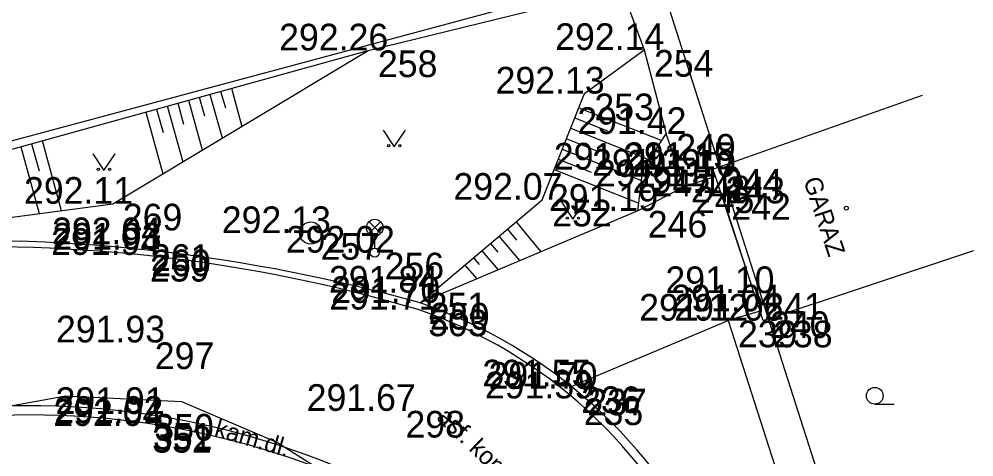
# Model space of a CAD drawing. Extents: x -599970 to -599524, y -1154772 to -1154457.
# Drawn here: x -599739.51 to -599718.03, y -1154670.86 to -1154661 of the extents above; entities that cross this region are included whole.
import ezdxf

# ---------------------------------------------------------------- set-up
doc = ezdxf.new("R2010")
doc.units = 0
for name, color, linetype in [('Z-BUDOVY', 7, 'Continuous'), ('Z-ELEKTRICKE SKRINE LAMPY', 7, 'Continuous'), ('Z-KANALIZACNI SACHTY VPUSTI', 7, 'Continuous'), ('Z-KATASTRALNI MAPA', 7, 'Continuous'), ('Z-PLOT DRATENY', 7, 'Continuous'), ('Z-PODROBNE BODY', 7, 'Continuous'), ('Z-PODROBNE BODY-CISLO', 7, 'Continuous'), ('Z-PODROBNE BODY-VYSKA', 7, 'Continuous'), ('Z-POPISY OBJEKTU A ZPEVNENYCH PLOCH', 7, 'Continuous'), ('Z-SCHODY', 7, 'Continuous'), ('Z-SRAFOVANI SVAHU', 7, 'Continuous'), ('Z-STROMY ZNACKY KULTUR', 7, 'Continuous'), ('Z-TERENNI HRANY PATY', 7, 'Continuous'), ('Z-VSTUPY VJEZDY', 7, 'Continuous'), ('Z-ZPEVNENE PLOCHY', 7, 'Continuous')]:
    doc.layers.add(name, color=color, linetype=linetype)

msp = doc.modelspace()

# ---------------------------------------------------------------- linework, layer by layer
at = {"layer": 'Z-BUDOVY'}
for p, q in [((-599723.9, -1154664.38), (-599719.19, -1154662.72)), ((-599722.77, -1154667.79), (-599718.03, -1154666.21))]:
    msp.add_line(p, q, dxfattribs=at)
msp.add_lwpolyline([(-599722.77, -1154667.79), (-599722.84, -1154667.58), (-599723.84, -1154664.55), (-599723.9, -1154664.38)], dxfattribs=at)
at = {"layer": 'Z-ELEKTRICKE SKRINE LAMPY'}
for p, q in [((-599731.642, -1154665.829), (-599731.378, -1154665.565)), ((-599731.374, -1154665.828), (-599731.638, -1154665.563)), ((-599731.51, -1154666.16), (-599731.51, -1154665.885))]:
    msp.add_line(p, q, dxfattribs=at)
for centre, radius in [((-599731.51, -1154665.698), 0.188), ((-599731.51, -1154666.26), 0.1)]:
    msp.add_circle(centre, radius, dxfattribs=at)
at = {"layer": 'Z-KANALIZACNI SACHTY VPUSTI'}
msp.add_circle((-599732.95, -1154665.82), 0.25, dxfattribs=at)
at = {"layer": 'Z-KATASTRALNI MAPA'}
for q in [(-599770.56, -1154672.04), (-599721.27, -1154672.07)]:
    msp.add_line((-599725.18, -1154659.85), q, dxfattribs=at)
msp.add_lwpolyline([(-599834.98, -1154699.48), (-599751.66, -1154673.18), (-599740.79, -1154669.9), (-599738.46, -1154669.48), (-599735.86, -1154669.61), (-599733.7, -1154670.53), (-599731.62, -1154671.85), (-599729.9, -1154673.34)], dxfattribs=at)
at = {"layer": 'Z-PLOT DRATENY'}
for points in [[(-599790.59, -1154625.68), (-599789.41, -1154629.89), (-599785.15, -1154644.86), (-599782.34, -1154653.87), (-599779.13, -1154664.86), (-599776.51, -1154673.7), (-599770.19, -1154672.08), (-599762.65, -1154670.15), (-599753.18, -1154667.49), (-599743.82, -1154665.08), (-599731.66, -1154661.71), (-599725.96, -1154660.31)], [(-599725.96, -1154660.31), (-599725.45, -1154661.7), (-599724.95, -1154663.59)], [(-599723.84, -1154664.55), (-599724.53, -1154664.77), (-599724.62, -1154664.53)], [(-599722.84, -1154667.58), (-599723.56, -1154667.79), (-599721.98, -1154672.69), (-599721.73, -1154673.41)]]:
    msp.add_lwpolyline(points, dxfattribs=at)
at = {"layer": 'Z-PODROBNE BODY'}
for p, q in [((-599731.66, -1154661.71), (-599731.66, -1154661.71)), ((-599725.45, -1154661.7), (-599725.45, -1154661.7)), ((-599726.79, -1154662.68), (-599726.79, -1154662.68)), ((-599724.95, -1154663.59), (-599724.95, -1154663.59)), ((-599725.48, -1154664.39), (-599725.48, -1154664.39)), ((-599723.9, -1154664.38), (-599723.9, -1154664.38)), ((-599724.62, -1154664.53), (-599724.62, -1154664.53)), ((-599723.84, -1154664.55), (-599723.84, -1154664.55)), ((-599724.53, -1154664.77), (-599724.53, -1154664.77)), ((-599727.74, -1154665.07), (-599727.74, -1154665.07)), ((-599723.71, -1154664.92), (-599723.71, -1154664.92)), ((-599737.4, -1154665.16), (-599737.4, -1154665.16)), ((-599725.59, -1154665.32), (-599725.59, -1154665.32)), ((-599732.95, -1154665.82), (-599732.95, -1154665.82)), ((-599736.77, -1154666.07), (-599736.77, -1154666.07)), ((-599736.76, -1154666.19), (-599736.76, -1154666.19)), ((-599736.79, -1154666.31), (-599736.79, -1154666.31)), ((-599731.51, -1154666.26), (-599731.51, -1154666.26)), ((-599730.54, -1154667.16), (-599730.54, -1154667.16)), ((-599722.97, -1154667.17), (-599722.97, -1154667.17)), ((-599730.49, -1154667.39), (-599730.49, -1154667.39)), ((-599730.53, -1154667.54), (-599730.53, -1154667.54)), ((-599722.84, -1154667.58), (-599722.84, -1154667.58)), ((-599723.56, -1154667.79), (-599723.56, -1154667.79)), ((-599722.77, -1154667.79), (-599722.77, -1154667.79)), ((-599736.68, -1154668.28), (-599736.68, -1154668.28)), ((-599727.09, -1154669.27), (-599727.09, -1154669.27)), ((-599726.95, -1154669.32), (-599726.95, -1154669.32)), ((-599727.03, -1154669.54), (-599727.03, -1154669.54)), ((-599731.04, -1154669.82), (-599731.04, -1154669.82)), ((-599736.69, -1154669.89), (-599736.69, -1154669.89)), ((-599736.74, -1154670.16), (-599736.74, -1154670.16)), ((-599736.72, -1154670.09), (-599736.72, -1154670.09))]:
    msp.add_line(p, q, dxfattribs=at)
at = {"layer": 'Z-SCHODY'}
msp.add_circle((-599720.9, -1154665.26), 0.0438, dxfattribs=at)
at = {"layer": 'Z-SRAFOVANI SVAHU'}
for points in [[(-599735.46, -1154662.76), (-599735.34, -1154663.18)], [(-599735.22, -1154662.7), (-599734.94, -1154663.68)], [(-599734.98, -1154662.63), (-599734.87, -1154663)], [(-599734.73, -1154662.56), (-599734.5, -1154663.42)], [(-599736.18, -1154662.96), (-599735.83, -1154664.22)], [(-599735.94, -1154662.9), (-599735.81, -1154663.37)], [(-599735.7, -1154662.83), (-599735.39, -1154663.95)], [(-599736.66, -1154663.1), (-599736.28, -1154664.49)], [(-599736.42, -1154663.03), (-599736.27, -1154663.56)], [(-599726.92, -1154663), (-599725.05, -1154663.74)], [(-599727.01, -1154663.23), (-599726.28, -1154663.52)], [(-599727.1, -1154663.46), (-599725.33, -1154664.17)], [(-599739.23, -1154663.81), (-599739.06, -1154664.42)], [(-599738.99, -1154663.74), (-599738.56, -1154665.31)], [(-599727.19, -1154663.7), (-599726.51, -1154663.97)], [(-599739.47, -1154663.88), (-599739.06, -1154665.38)], [(-599727.29, -1154663.93), (-599725.51, -1154664.64)], [(-599727.38, -1154664.16), (-599726.64, -1154664.45)], [(-599727.47, -1154664.39), (-599725.57, -1154665.15)], [(-599728.52, -1154665.73), (-599728.32, -1154665.98)], [(-599728.33, -1154665.57), (-599727.77, -1154666.24)], [(-599728.72, -1154665.89), (-599728.25, -1154666.44)], [(-599728.91, -1154666.05), (-599728.74, -1154666.25)], [(-599729.29, -1154666.38), (-599729.16, -1154666.53)], [(-599729.1, -1154666.22), (-599728.73, -1154666.65)], [(-599729.48, -1154666.54), (-599729.21, -1154666.85)]]:
    msp.add_lwpolyline(points, dxfattribs=at)
at = {"layer": 'Z-STROMY ZNACKY KULTUR'}
msp.add_line((-599720.26, -1154669.668), (-599719.822, -1154669.668), dxfattribs=at)
for points in [[(-599731.32, -1154663.505), (-599731.07, -1154663.88), (-599730.82, -1154663.505)], [(-599737.85, -1154664.035), (-599737.6, -1154664.41), (-599737.35, -1154664.035)], [(-599727.3, -1154665.135), (-599727.05, -1154665.51), (-599726.8, -1154665.135)]]:
    msp.add_lwpolyline(points, dxfattribs=at)
for centre, radius in [((-599731.195, -1154663.855), 0.025), ((-599730.945, -1154663.855), 0.025), ((-599737.725, -1154664.385), 0.025), ((-599737.475, -1154664.385), 0.025), ((-599727.175, -1154665.485), 0.025), ((-599726.925, -1154665.485), 0.025), ((-599720.26, -1154669.48), 0.188)]:
    msp.add_circle(centre, radius, dxfattribs=at)
at = {"layer": 'Z-TERENNI HRANY PATY'}
for points in [[(-599742.26, -1154667.02), (-599742.5, -1154665.84), (-599737.4, -1154665.16), (-599731.66, -1154661.71)], [(-599730.49, -1154667.39), (-599727.74, -1154665.07), (-599726.79, -1154662.68), (-599725.45, -1154661.7)]]:
    msp.add_lwpolyline(points, dxfattribs=at)
at = {"layer": 'Z-VSTUPY VJEZDY'}
for points in [[(-599724.62, -1154664.53), (-599724.95, -1154663.59)], [(-599722.97, -1154667.17), (-599723.71, -1154664.92)]]:
    msp.add_lwpolyline(points, dxfattribs=at)
at = {"layer": 'Z-ZPEVNENE PLOCHY'}
for points in [[(-599725.59, -1154665.32), (-599725.48, -1154664.39), (-599724.95, -1154663.59)], [(-599724.53, -1154664.77), (-599725.59, -1154665.32), (-599730.49, -1154667.39)], [(-599727.09, -1154669.27), (-599723.56, -1154667.79)]]:
    msp.add_lwpolyline(points, dxfattribs=at)
for centre, radius, start, end in [((-599740.676, -1154703.63), 37.644, 74.3013, 92.4426), ((-599740.37, -1154701.075), 34.949, 73.647, 92.8702), ((-599734.212, -1154678.135), 11.372, 25.0528, 70.8958), ((-599734.095, -1154677.842), 10.901, 24.0446, 70.9101), ((-599739.28, -1154687.811), 18.107, 64.483, 98.8632), ((-599739.271, -1154688.14), 18.229, 64.7672, 98.4821)]:
    msp.add_arc(centre, radius, start, end, dxfattribs=at)

# ---------------------------------------------------------------- texts
at = {"layer": 'Z-PODROBNE BODY-CISLO'}
for s, p in [(' 254', (-599725.45, -1154662.3)), (' 258', (-599731.66, -1154662.31)), (' 253', (-599726.79, -1154663.28)), (' 249', (-599724.95, -1154664.19)), (' 247', (-599725.48, -1154664.99)), (' 244', (-599723.9, -1154664.98)), (' 248', (-599724.62, -1154665.13)), (' 243', (-599723.84, -1154665.15)), (' 245', (-599724.53, -1154665.37)), (' 242', (-599723.71, -1154665.52)), (' 252', (-599727.74, -1154665.67)), (' 269', (-599737.4, -1154665.76)), (' 246', (-599725.59, -1154665.92)), (' 257', (-599732.95, -1154666.42)), (' 261', (-599736.77, -1154666.67)), (' 260', (-599736.76, -1154666.79)), (' 259', (-599736.79, -1154666.91)), (' 256', (-599731.51, -1154666.86)), (' 251', (-599730.54, -1154667.76)), (' 241', (-599722.97, -1154667.77)), (' 250', (-599730.49, -1154667.99)), (' 503', (-599730.53, -1154668.14)), (' 240', (-599722.84, -1154668.18)), (' 239', (-599723.56, -1154668.39)), (' 238', (-599722.77, -1154668.39)), (' 297', (-599736.68, -1154668.88)), (' 236', (-599727.09, -1154669.87)), (' 237', (-599726.95, -1154669.92)), (' 235', (-599727.03, -1154670.14)), (' 298', (-599731.04, -1154670.42)), (' 350', (-599736.69, -1154670.49)), (' 352', (-599736.74, -1154670.76)), (' 351', (-599736.72, -1154670.69))]:
    msp.add_text(s, height=0.6, dxfattribs=at).set_placement(p)
at = {"layer": 'Z-PODROBNE BODY-VYSKA'}
for s, p in [('292.26 ', (-599733.66, -1154661.71)), ('292.14 ', (-599727.45, -1154661.7)), ('292.13 ', (-599728.79, -1154662.68)), ('291.42 ', (-599726.95, -1154663.59)), ('291.21 ', (-599727.48, -1154664.39)), ('291.15 ', (-599725.9, -1154664.38)), ('291.39 ', (-599726.62, -1154664.53)), ('291.10 ', (-599725.84, -1154664.55)), ('291.11 ', (-599726.53, -1154664.77)), ('292.07 ', (-599729.74, -1154665.07)), ('291.10 ', (-599725.71, -1154664.92)), ('292.11 ', (-599739.4, -1154665.16)), ('291.19 ', (-599727.59, -1154665.32)), ('292.13 ', (-599734.95, -1154665.82)), ('292.04 ', (-599738.77, -1154666.07)), ('291.94 ', (-599738.79, -1154666.31)), ('291.93 ', (-599738.76, -1154666.19)), ('292.02 ', (-599733.51, -1154666.26)), ('291.84 ', (-599732.54, -1154667.16)), ('291.10 ', (-599724.97, -1154667.17)), ('291.70 ', (-599732.49, -1154667.39)), ('291.71 ', (-599732.53, -1154667.54)), ('291.04 ', (-599724.84, -1154667.58)), ('291.12 ', (-599725.56, -1154667.79)), ('291.06 ', (-599724.77, -1154667.79)), ('291.93 ', (-599738.68, -1154668.28)), ('291.55 ', (-599729.09, -1154669.27)), ('291.70 ', (-599728.95, -1154669.32)), ('291.59 ', (-599729.03, -1154669.54)), ('291.67 ', (-599733.04, -1154669.82)), ('291.91 ', (-599738.69, -1154669.89)), ('292.04 ', (-599738.74, -1154670.16)), ('291.92 ', (-599738.72, -1154670.09))]:
    msp.add_text(s, height=0.6, dxfattribs=at).set_placement(p)
at = {"layer": 'Z-POPISY OBJEKTU A ZPEVNENYCH PLOCH'}
for s, rotation, p in [('GARAZ', 288.2055, (-599721.87, -1154664.63)), ('asf. komunikace', 316.0414, (-599730.14, -1154669.99)), ('kam.dl.', 343.6733, (-599735.14, -1154670.38))]:
    msp.add_text(s, height=0.4, rotation=rotation, dxfattribs=at).set_placement(p)

doc.saveas('drawing.dxf')
